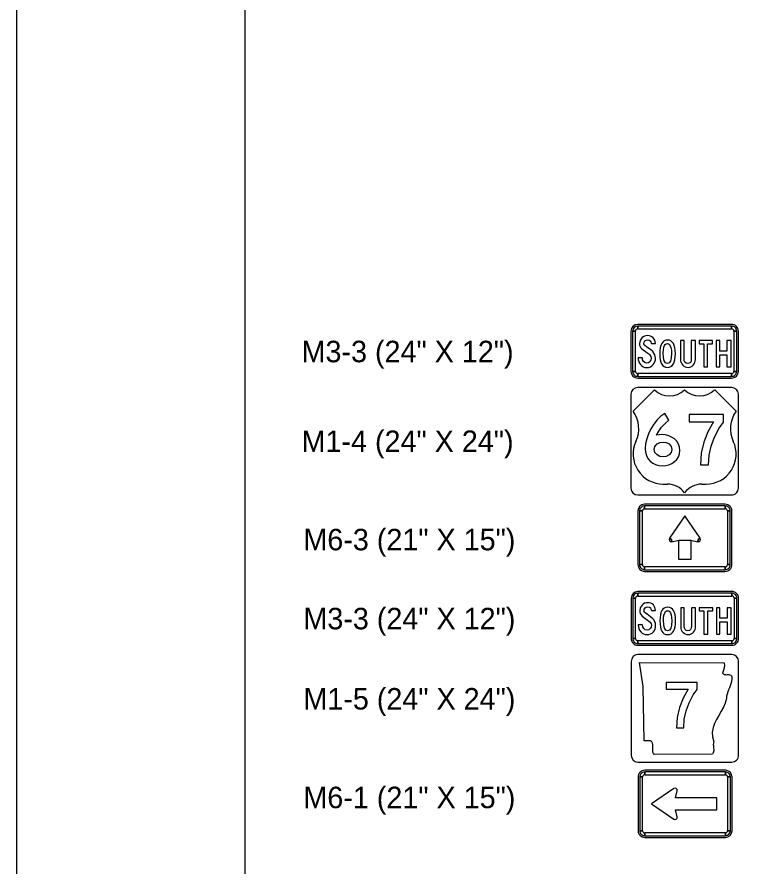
# Model space of a CAD drawing. Extents: x 1001568 to 1002149, y 1840825 to 1841423.
# Drawn here: x 1001886.41 to 1001900.1, y 1841178.92 to 1841194.75 of the extents above; entities that cross this region are included whole.
import ezdxf

# ---------------------------------------------------------------- set-up
doc = ezdxf.new("R2010")
doc.units = 0
for name, color, linetype in [('40', 7, 'Continuous'), ('R_No Plot', 7, 'Continuous'), ('SIGNS', 7, 'Continuous')]:
    doc.layers.add(name, color=color, linetype=linetype)

msp = doc.modelspace()

# ---------------------------------------------------------------- linework, layer by layer
at = {"layer": 'R_No Plot'}
msp.add_line((1001890.65, 1841210.667), (1001890.65, 1841148.127), dxfattribs=at)
msp.add_lwpolyline([(1001886.411, 1841210.667), (1001964.232, 1841210.667), (1001964.232, 1841207.694), (1001968.454, 1841207.694), (1001968.454, 1841206.882), (1001982.133, 1841206.882), (1001982.133, 1841148.127), (1001886.411, 1841148.127)], close=True, dxfattribs=at)
at = {"layer": 'SIGNS'}
for p, q in [((1001897.842, 1841188.897), (1001897.842, 1841188.147)), ((1001897.873, 1841188.897), (1001897.925, 1841188.897)), ((1001899.717, 1841189.022), (1001897.967, 1841189.022)), ((1001897.967, 1841188.939), (1001897.967, 1841188.991)), ((1001899.717, 1841188.991), (1001899.717, 1841188.939)), ((1001899.758, 1841188.897), (1001899.811, 1841188.897)), ((1001899.842, 1841188.147), (1001899.842, 1841188.897)), ((1001897.925, 1841188.147), (1001897.873, 1841188.147)), ((1001897.967, 1841188.053), (1001897.967, 1841188.105)), ((1001899.717, 1841188.105), (1001899.717, 1841188.053)), ((1001899.811, 1841188.147), (1001899.758, 1841188.147)), ((1001897.967, 1841188.022), (1001899.717, 1841188.022)), ((1001898.283, 1841187.805), (1001897.883, 1841187.405)), ((1001899.717, 1841187.846), (1001897.967, 1841187.846)), ((1001899.8, 1841187.405), (1001899.401, 1841187.805)), ((1001897.842, 1841187.721), (1001897.842, 1841185.971)), ((1001899.842, 1841185.971), (1001899.842, 1841187.721)), ((1001898.442, 1841186.048), (1001898.522, 1841186.048)), ((1001899.161, 1841186.048), (1001899.241, 1841186.048)), ((1001897.842, 1841185.971), (1001897.842, 1841185.971)), ((1001897.967, 1841185.846), (1001899.717, 1841185.846)), ((1001899.596, 1841185.673), (1001898.096, 1841185.673)), ((1001898.096, 1841185.589), (1001898.096, 1841185.641)), ((1001899.596, 1841185.641), (1001899.596, 1841185.589)), ((1001897.971, 1841185.548), (1001897.971, 1841184.548)), ((1001898.002, 1841185.548), (1001898.054, 1841185.548)), ((1001899.637, 1841185.548), (1001899.689, 1841185.548)), ((1001899.721, 1841184.548), (1001899.721, 1841185.548)), ((1001898.596, 1841185.016), (1001898.56, 1841185.039)), ((1001898.605, 1841184.976), (1001898.596, 1841185.016)), ((1001899.096, 1841185.016), (1001899.086, 1841184.976)), ((1001899.131, 1841185.039), (1001899.096, 1841185.016)), ((1001898.054, 1841184.548), (1001898.002, 1841184.548)), ((1001898.096, 1841184.454), (1001898.096, 1841184.506)), ((1001899.596, 1841184.506), (1001899.596, 1841184.454)), ((1001899.689, 1841184.548), (1001899.637, 1841184.548)), ((1001898.096, 1841184.423), (1001899.596, 1841184.423)), ((1001899.721, 1841184.048), (1001897.971, 1841184.048)), ((1001897.971, 1841183.964), (1001897.971, 1841184.016)), ((1001899.721, 1841184.016), (1001899.721, 1841183.964)), ((1001897.846, 1841183.923), (1001897.846, 1841183.173)), ((1001897.877, 1841183.923), (1001897.929, 1841183.923)), ((1001899.762, 1841183.923), (1001899.814, 1841183.923)), ((1001899.846, 1841183.173), (1001899.846, 1841183.923)), ((1001897.929, 1841183.173), (1001897.877, 1841183.173)), ((1001897.971, 1841183.079), (1001897.971, 1841183.131)), ((1001897.971, 1841183.048), (1001899.721, 1841183.048)), ((1001899.721, 1841183.131), (1001899.721, 1841183.079)), ((1001899.814, 1841183.173), (1001899.762, 1841183.173)), ((1001899.721, 1841182.872), (1001897.971, 1841182.872)), ((1001897.846, 1841182.747), (1001897.846, 1841180.997)), ((1001899.846, 1841180.997), (1001899.846, 1841182.747)), ((1001897.846, 1841180.997), (1001897.846, 1841180.997)), ((1001897.971, 1841180.872), (1001899.721, 1841180.872)), ((1001899.6, 1841180.719), (1001898.1, 1841180.719)), ((1001898.1, 1841180.636), (1001898.1, 1841180.688)), ((1001899.6, 1841180.688), (1001899.6, 1841180.636)), ((1001897.975, 1841180.594), (1001897.975, 1841179.594)), ((1001898.006, 1841180.594), (1001898.058, 1841180.594)), ((1001899.641, 1841180.594), (1001899.693, 1841180.594)), ((1001899.725, 1841179.594), (1001899.725, 1841180.594)), ((1001898.64, 1841180.379), (1001898.225, 1841180.094)), ((1001898.673, 1841180.203), (1001898.703, 1841180.335)), ((1001899.443, 1841180.203), (1001898.673, 1841180.203)), ((1001899.443, 1841180.203), (1001899.443, 1841180.203)), ((1001899.443, 1841179.985), (1001899.443, 1841180.203)), ((1001898.225, 1841180.094), (1001898.225, 1841180.094)), ((1001898.225, 1841180.094), (1001898.64, 1841179.809)), ((1001898.703, 1841179.853), (1001898.673, 1841179.985)), ((1001898.673, 1841179.985), (1001899.443, 1841179.985)), ((1001898.058, 1841179.594), (1001898.006, 1841179.594)), ((1001898.1, 1841179.5), (1001898.1, 1841179.552)), ((1001899.6, 1841179.552), (1001899.6, 1841179.5)), ((1001899.693, 1841179.594), (1001899.641, 1841179.594)), ((1001898.1, 1841179.469), (1001899.6, 1841179.469))]:
    msp.add_line(p, q, dxfattribs=at)
for points in [[(1001897.873, 1841188.897), (1001897.873, 1841188.147), (1001897.925, 1841188.147), (1001897.925, 1841188.897), (1001897.873, 1841188.897), (1001897.873, 1841188.897)], [(1001899.717, 1841188.991), (1001897.967, 1841188.991), (1001897.967, 1841188.939), (1001899.717, 1841188.939), (1001899.717, 1841188.991), (1001899.717, 1841188.991)], [(1001899.811, 1841188.147), (1001899.811, 1841188.897), (1001899.758, 1841188.897), (1001899.758, 1841188.147), (1001899.811, 1841188.147), (1001899.811, 1841188.147)], [(1001897.975, 1841188.402), (1001897.975, 1841188.397), (1001897.978, 1841188.362), (1001897.986, 1841188.33), (1001898, 1841188.3), (1001898.02, 1841188.273), (1001898.044, 1841188.249), (1001898.072, 1841188.233), (1001898.103, 1841188.222), (1001898.137, 1841188.219), (1001898.172, 1841188.222), (1001898.203, 1841188.232), (1001898.23, 1841188.249), (1001898.255, 1841188.272), (1001898.274, 1841188.298), (1001898.287, 1841188.327), (1001898.296, 1841188.359), (1001898.298, 1841188.394), (1001898.295, 1841188.427), (1001898.285, 1841188.458), (1001898.269, 1841188.488), (1001898.247, 1841188.517), (1001898.204, 1841188.554), (1001898.137, 1841188.599), (1001898.094, 1841188.632), (1001898.084, 1841188.649), (1001898.081, 1841188.668), (1001898.086, 1841188.694), (1001898.101, 1841188.715), (1001898.124, 1841188.73), (1001898.15, 1841188.735), (1001898.179, 1841188.73), (1001898.199, 1841188.716), (1001898.21, 1841188.697), (1001898.219, 1841188.668), (1001898.298, 1841188.668), (1001898.285, 1841188.726), (1001898.255, 1841188.772), (1001898.233, 1841188.79), (1001898.208, 1841188.803), (1001898.179, 1841188.811), (1001898.148, 1841188.814), (1001898.119, 1841188.811), (1001898.092, 1841188.803), (1001898.067, 1841188.789), (1001898.045, 1841188.769), (1001898.012, 1841188.721), (1001898.001, 1841188.666), (1001898.004, 1841188.637), (1001898.012, 1841188.611), (1001898.026, 1841188.586), (1001898.045, 1841188.564), (1001898.138, 1841188.498), (1001898.173, 1841188.472), (1001898.194, 1841188.452), (1001898.213, 1841188.423), (1001898.219, 1841188.393), (1001898.214, 1841188.359), (1001898.197, 1841188.33), (1001898.17, 1841188.309), (1001898.137, 1841188.302), (1001898.102, 1841188.31), (1001898.075, 1841188.334), (1001898.059, 1841188.365), (1001898.054, 1841188.402)], [(1001898.764, 1841188.721), (1001898.764, 1841188.366), (1001898.767, 1841188.337), (1001898.775, 1841188.31), (1001898.787, 1841188.286), (1001898.805, 1841188.263), (1001898.826, 1841188.245), (1001898.85, 1841188.231), (1001898.876, 1841188.223), (1001898.905, 1841188.221), (1001898.932, 1841188.223), (1001898.958, 1841188.232), (1001898.981, 1841188.246), (1001899.002, 1841188.265), (1001899.019, 1841188.288), (1001899.031, 1841188.312), (1001899.038, 1841188.339), (1001899.041, 1841188.367), (1001899.041, 1841188.721), (1001898.966, 1841188.721), (1001898.966, 1841188.37), (1001898.962, 1841188.339), (1001898.949, 1841188.315), (1001898.926, 1841188.297), (1001898.897, 1841188.292), (1001898.869, 1841188.298), (1001898.848, 1841188.316), (1001898.835, 1841188.341), (1001898.831, 1841188.37), (1001898.831, 1841188.721)], [(1001899.198, 1841188.23), (1001899.269, 1841188.23), (1001899.269, 1841188.659), (1001899.361, 1841188.659), (1001899.361, 1841188.721), (1001899.109, 1841188.721), (1001899.109, 1841188.659), (1001899.198, 1841188.659)], [(1001899.428, 1841188.23), (1001899.495, 1841188.23), (1001899.495, 1841188.455), (1001899.63, 1841188.455), (1001899.63, 1841188.23), (1001899.705, 1841188.23), (1001899.705, 1841188.721), (1001899.63, 1841188.721), (1001899.63, 1841188.524), (1001899.495, 1841188.524), (1001899.495, 1841188.721), (1001899.428, 1841188.721)], [(1001897.967, 1841188.053), (1001899.717, 1841188.053), (1001899.717, 1841188.105), (1001897.967, 1841188.105), (1001897.967, 1841188.053), (1001897.967, 1841188.053)], [(1001899.134, 1841186.407), (1001899.286, 1841186.407), (1001899.298, 1841186.584), (1001899.335, 1841186.757), (1001899.397, 1841186.924), (1001899.484, 1841187.088), (1001899.568, 1841187.2), (1001899.568, 1841187.347), (1001898.923, 1841187.347), (1001898.923, 1841187.206), (1001899.377, 1841187.206), (1001899.272, 1841187.022), (1001899.197, 1841186.827), (1001899.151, 1841186.622)], [(1001899.596, 1841185.641), (1001898.096, 1841185.641), (1001898.096, 1841185.589), (1001899.596, 1841185.589), (1001899.596, 1841185.641), (1001899.596, 1841185.641)], [(1001898.002, 1841185.548), (1001898.002, 1841184.548), (1001898.054, 1841184.548), (1001898.054, 1841185.548), (1001898.002, 1841185.548), (1001898.002, 1841185.548)], [(1001898.846, 1841185.454), (1001898.56, 1841185.039), (1001898.596, 1841185.016), (1001898.605, 1841184.976), (1001898.736, 1841185.006), (1001898.955, 1841185.006), (1001899.086, 1841184.976), (1001899.096, 1841185.016), (1001899.131, 1841185.039), (1001898.846, 1841185.454), (1001898.846, 1841185.454)], [(1001899.689, 1841184.548), (1001899.689, 1841185.548), (1001899.637, 1841185.548), (1001899.637, 1841184.548), (1001899.689, 1841184.548), (1001899.689, 1841184.548)], [(1001898.955, 1841184.641), (1001898.736, 1841184.641), (1001898.736, 1841185.006), (1001898.955, 1841185.006), (1001898.955, 1841184.641), (1001898.955, 1841184.641)], [(1001898.096, 1841184.454), (1001899.596, 1841184.454), (1001899.596, 1841184.506), (1001898.096, 1841184.506), (1001898.096, 1841184.454), (1001898.096, 1841184.454)], [(1001899.721, 1841184.016), (1001897.971, 1841184.016), (1001897.971, 1841183.964), (1001899.721, 1841183.964), (1001899.721, 1841184.016), (1001899.721, 1841184.016)], [(1001897.877, 1841183.923), (1001897.877, 1841183.173), (1001897.929, 1841183.173), (1001897.929, 1841183.923), (1001897.877, 1841183.923), (1001897.877, 1841183.923)], [(1001897.979, 1841183.428), (1001897.979, 1841183.423), (1001897.982, 1841183.388), (1001897.99, 1841183.356), (1001898.004, 1841183.326), (1001898.024, 1841183.299), (1001898.048, 1841183.275), (1001898.076, 1841183.258), (1001898.107, 1841183.248), (1001898.141, 1841183.245), (1001898.175, 1841183.248), (1001898.206, 1841183.258), (1001898.234, 1841183.274), (1001898.259, 1841183.297), (1001898.278, 1841183.324), (1001898.291, 1841183.353), (1001898.3, 1841183.385), (1001898.302, 1841183.419), (1001898.299, 1841183.453), (1001898.289, 1841183.484), (1001898.273, 1841183.514), (1001898.251, 1841183.542), (1001898.208, 1841183.579), (1001898.141, 1841183.625), (1001898.097, 1841183.658), (1001898.088, 1841183.675), (1001898.085, 1841183.694), (1001898.09, 1841183.719), (1001898.105, 1841183.741), (1001898.128, 1841183.755), (1001898.154, 1841183.76), (1001898.182, 1841183.755), (1001898.203, 1841183.742), (1001898.214, 1841183.722), (1001898.223, 1841183.694), (1001898.302, 1841183.694), (1001898.289, 1841183.752), (1001898.259, 1841183.798), (1001898.237, 1841183.816), (1001898.212, 1841183.829), (1001898.183, 1841183.837), (1001898.152, 1841183.839), (1001898.123, 1841183.836), (1001898.096, 1841183.828), (1001898.071, 1841183.814), (1001898.049, 1841183.795), (1001898.016, 1841183.747), (1001898.005, 1841183.691), (1001898.008, 1841183.663), (1001898.016, 1841183.636), (1001898.03, 1841183.612), (1001898.049, 1841183.59), (1001898.142, 1841183.523), (1001898.177, 1841183.497), (1001898.198, 1841183.478), (1001898.217, 1841183.449), (1001898.223, 1841183.419), (1001898.218, 1841183.385), (1001898.201, 1841183.356), (1001898.174, 1841183.335), (1001898.141, 1841183.328), (1001898.106, 1841183.336), (1001898.079, 1841183.359), (1001898.063, 1841183.39), (1001898.058, 1841183.428)], [(1001899.814, 1841183.173), (1001899.814, 1841183.923), (1001899.762, 1841183.923), (1001899.762, 1841183.173), (1001899.814, 1841183.173), (1001899.814, 1841183.173)], [(1001898.768, 1841183.746), (1001898.768, 1841183.391), (1001898.771, 1841183.362), (1001898.779, 1841183.336), (1001898.791, 1841183.311), (1001898.809, 1841183.289), (1001898.83, 1841183.27), (1001898.854, 1841183.257), (1001898.88, 1841183.249), (1001898.908, 1841183.246), (1001898.936, 1841183.249), (1001898.962, 1841183.257), (1001898.985, 1841183.271), (1001899.006, 1841183.291), (1001899.023, 1841183.314), (1001899.035, 1841183.338), (1001899.042, 1841183.364), (1001899.045, 1841183.393), (1001899.045, 1841183.746), (1001898.97, 1841183.746), (1001898.97, 1841183.396), (1001898.966, 1841183.365), (1001898.953, 1841183.341), (1001898.93, 1841183.323), (1001898.901, 1841183.317), (1001898.873, 1841183.323), (1001898.852, 1841183.342), (1001898.839, 1841183.366), (1001898.835, 1841183.396), (1001898.835, 1841183.746)], [(1001899.202, 1841183.256), (1001899.273, 1841183.256), (1001899.273, 1841183.685), (1001899.365, 1841183.685), (1001899.365, 1841183.746), (1001899.113, 1841183.746), (1001899.113, 1841183.685), (1001899.202, 1841183.685)], [(1001899.432, 1841183.256), (1001899.499, 1841183.256), (1001899.499, 1841183.481), (1001899.634, 1841183.481), (1001899.634, 1841183.256), (1001899.709, 1841183.256), (1001899.709, 1841183.746), (1001899.634, 1841183.746), (1001899.634, 1841183.55), (1001899.499, 1841183.55), (1001899.499, 1841183.746), (1001899.432, 1841183.746)], [(1001897.971, 1841183.079), (1001899.721, 1841183.079), (1001899.721, 1841183.131), (1001897.971, 1841183.131), (1001897.971, 1841183.079), (1001897.971, 1841183.079)], [(1001899.576, 1841182.718), (1001899.58, 1841182.699), (1001899.582, 1841182.679), (1001899.581, 1841182.66), (1001899.579, 1841182.641), (1001899.575, 1841182.622), (1001899.57, 1841182.603), (1001899.565, 1841182.584), (1001899.559, 1841182.566), (1001899.554, 1841182.547), (1001899.549, 1841182.529), (1001899.563, 1841182.513), (1001899.58, 1841182.504), (1001899.6, 1841182.5), (1001899.621, 1841182.499), (1001899.642, 1841182.5), (1001899.663, 1841182.5), (1001899.682, 1841182.498), (1001899.699, 1841182.492), (1001899.712, 1841182.48), (1001899.72, 1841182.46), (1001899.721, 1841182.414), (1001899.715, 1841182.371), (1001899.704, 1841182.331), (1001899.69, 1841182.292), (1001899.674, 1841182.254), (1001899.658, 1841182.216), (1001899.643, 1841182.178), (1001899.631, 1841182.138), (1001899.623, 1841182.097), (1001899.621, 1841182.053), (1001899.599, 1841181.971), (1001899.565, 1841181.892), (1001899.524, 1841181.817), (1001899.48, 1841181.742), (1001899.437, 1841181.667), (1001899.399, 1841181.591), (1001899.371, 1841181.513), (1001899.357, 1841181.43), (1001899.36, 1841181.343), (1001899.386, 1841181.249), (1001899.378, 1841181.226), (1001899.375, 1841181.202), (1001899.376, 1841181.178), (1001899.379, 1841181.154), (1001899.382, 1841181.13), (1001899.385, 1841181.107), (1001899.386, 1841181.084), (1001899.382, 1841181.062), (1001899.374, 1841181.041), (1001899.359, 1841181.021), (1001898.275, 1841181.011), (1001898.26, 1841181.031), (1001898.252, 1841181.055), (1001898.248, 1841181.081), (1001898.248, 1841181.109), (1001898.249, 1841181.139), (1001898.249, 1841181.168), (1001898.247, 1841181.197), (1001898.241, 1841181.224), (1001898.23, 1841181.248), (1001898.212, 1841181.269), (1001898.086, 1841181.269), (1001898.067, 1841182.281), (1001898.004, 1841182.728), (1001899.576, 1841182.718), (1001899.576, 1841182.718)], [(1001898.688, 1841181.512), (1001898.824, 1841181.512), (1001898.835, 1841181.67), (1001898.868, 1841181.825), (1001898.924, 1841181.975), (1001899.001, 1841182.121), (1001899.076, 1841182.221), (1001899.076, 1841182.353), (1001898.499, 1841182.353), (1001898.499, 1841182.227), (1001898.906, 1841182.227), (1001898.812, 1841182.062), (1001898.744, 1841181.888), (1001898.703, 1841181.704)], [(1001899.6, 1841180.688), (1001898.1, 1841180.688), (1001898.1, 1841180.636), (1001899.6, 1841180.636), (1001899.6, 1841180.688), (1001899.6, 1841180.688)], [(1001898.006, 1841180.594), (1001898.006, 1841179.594), (1001898.058, 1841179.594), (1001898.058, 1841180.594), (1001898.006, 1841180.594), (1001898.006, 1841180.594)], [(1001899.693, 1841179.594), (1001899.693, 1841180.594), (1001899.641, 1841180.594), (1001899.641, 1841179.594), (1001899.693, 1841179.594), (1001899.693, 1841179.594)], [(1001898.1, 1841179.5), (1001899.6, 1841179.5), (1001899.6, 1841179.552), (1001898.1, 1841179.552), (1001898.1, 1841179.5), (1001898.1, 1841179.5)]]:
    msp.add_lwpolyline(points, close=True, dxfattribs=at)
for points in [[(1001898.669, 1841188.476), (1001898.666, 1841188.536), (1001898.66, 1841188.587), (1001898.648, 1841188.631), (1001898.632, 1841188.667), (1001898.612, 1841188.694), (1001898.587, 1841188.714), (1001898.558, 1841188.726), (1001898.524, 1841188.73), (1001898.489, 1841188.726), (1001898.459, 1841188.714), (1001898.434, 1841188.694), (1001898.414, 1841188.667), (1001898.397, 1841188.631), (1001898.386, 1841188.587), (1001898.379, 1841188.536), (1001898.377, 1841188.476), (1001898.379, 1841188.416), (1001898.386, 1841188.364), (1001898.397, 1841188.32), (1001898.413, 1841188.285), (1001898.433, 1841188.256), (1001898.458, 1841188.237), (1001898.487, 1841188.225), (1001898.521, 1841188.221), (1001898.555, 1841188.225), (1001898.585, 1841188.237), (1001898.611, 1841188.256), (1001898.632, 1841188.285), (1001898.648, 1841188.32), (1001898.659, 1841188.364), (1001898.666, 1841188.416), (1001898.669, 1841188.476)], [(1001898.598, 1841188.478), (1001898.593, 1841188.397), (1001898.579, 1841188.339), (1001898.555, 1841188.304), (1001898.522, 1841188.292), (1001898.488, 1841188.304), (1001898.463, 1841188.342), (1001898.449, 1841188.404), (1001898.444, 1841188.491), (1001898.447, 1841188.549), (1001898.457, 1841188.597), (1001898.468, 1841188.626), (1001898.482, 1841188.647), (1001898.5, 1841188.66), (1001898.522, 1841188.664), (1001898.543, 1841188.66), (1001898.561, 1841188.646), (1001898.575, 1841188.623), (1001898.586, 1841188.59), (1001898.595, 1841188.539), (1001898.598, 1841188.478)], [(1001897.967, 1841187.846), (1001897.967, 1841187.846)], [(1001899.717, 1841187.846), (1001899.717, 1841187.846)], [(1001897.842, 1841187.721), (1001897.842, 1841187.721)], [(1001898.55, 1841187.241), (1001898.475, 1841187.365), (1001898.4, 1841187.31), (1001898.331, 1841187.244), (1001898.269, 1841187.167), (1001898.214, 1841187.079), (1001898.167, 1841186.985), (1001898.135, 1841186.892), (1001898.115, 1841186.8), (1001898.109, 1841186.709), (1001898.114, 1841186.641), (1001898.131, 1841186.58), (1001898.159, 1841186.525), (1001898.199, 1841186.478), (1001898.247, 1841186.438), (1001898.302, 1841186.411), (1001898.364, 1841186.394), (1001898.432, 1841186.389), (1001898.492, 1841186.393), (1001898.55, 1841186.408), (1001898.602, 1841186.432), (1001898.652, 1841186.466), (1001898.696, 1841186.509), (1001898.728, 1841186.558), (1001898.747, 1841186.612), (1001898.753, 1841186.672), (1001898.746, 1841186.735), (1001898.727, 1841186.793), (1001898.695, 1841186.845), (1001898.65, 1841186.89), (1001898.6, 1841186.925), (1001898.545, 1841186.949), (1001898.485, 1841186.964), (1001898.419, 1841186.969), (1001898.318, 1841186.959), (1001898.36, 1841187.036), (1001898.413, 1841187.109), (1001898.477, 1841187.177), (1001898.55, 1841187.241)], [(1001898.274, 1841186.694), (1001898.288, 1841186.75), (1001898.328, 1841186.796), (1001898.38, 1841186.822), (1001898.439, 1841186.831), (1001898.498, 1841186.822), (1001898.551, 1841186.796), (1001898.592, 1841186.75), (1001898.606, 1841186.694), (1001898.592, 1841186.636), (1001898.551, 1841186.59), (1001898.498, 1841186.563), (1001898.439, 1841186.555), (1001898.38, 1841186.563), (1001898.328, 1841186.59), (1001898.288, 1841186.636), (1001898.274, 1841186.694)], [(1001897.967, 1841185.846), (1001897.967, 1841185.846)], [(1001899.717, 1841185.846), (1001899.717, 1841185.846)], [(1001898.673, 1841183.502), (1001898.67, 1841183.561), (1001898.663, 1841183.613), (1001898.652, 1841183.656), (1001898.636, 1841183.692), (1001898.616, 1841183.72), (1001898.591, 1841183.74), (1001898.562, 1841183.752), (1001898.528, 1841183.756), (1001898.493, 1841183.752), (1001898.463, 1841183.74), (1001898.438, 1841183.72), (1001898.417, 1841183.692), (1001898.401, 1841183.656), (1001898.39, 1841183.613), (1001898.383, 1841183.561), (1001898.381, 1841183.502), (1001898.383, 1841183.442), (1001898.39, 1841183.39), (1001898.401, 1841183.346), (1001898.417, 1841183.31), (1001898.437, 1841183.282), (1001898.462, 1841183.262), (1001898.491, 1841183.25), (1001898.525, 1841183.246), (1001898.559, 1841183.25), (1001898.589, 1841183.262), (1001898.615, 1841183.282), (1001898.636, 1841183.31), (1001898.652, 1841183.346), (1001898.663, 1841183.39), (1001898.67, 1841183.442), (1001898.673, 1841183.502)], [(1001898.602, 1841183.504), (1001898.597, 1841183.422), (1001898.583, 1841183.364), (1001898.559, 1841183.329), (1001898.525, 1841183.318), (1001898.492, 1841183.33), (1001898.467, 1841183.367), (1001898.453, 1841183.429), (1001898.448, 1841183.516), (1001898.451, 1841183.574), (1001898.46, 1841183.622), (1001898.472, 1841183.652), (1001898.486, 1841183.673), (1001898.504, 1841183.686), (1001898.525, 1841183.69), (1001898.547, 1841183.685), (1001898.564, 1841183.671), (1001898.579, 1841183.648), (1001898.59, 1841183.616), (1001898.599, 1841183.565), (1001898.602, 1841183.504)], [(1001897.971, 1841182.872), (1001897.971, 1841182.872)], [(1001899.721, 1841182.872), (1001899.721, 1841182.872)], [(1001897.846, 1841182.747), (1001897.846, 1841182.747)], [(1001897.971, 1841180.872), (1001897.971, 1841180.872)], [(1001899.721, 1841180.872), (1001899.721, 1841180.872)]]:
    msp.add_lwpolyline(points, dxfattribs=at)
for centre, radius, start, end in [((1001897.967, 1841188.897), 0.125, 90.0002, 179.9998), ((1001897.967, 1841188.897), 0.0937, 90.0002, 179.9998), ((1001897.967, 1841188.897), 0.0417, 90.0002, 179.9998), ((1001899.717, 1841188.897), 0.125, 360, 90.0002), ((1001899.717, 1841188.897), 0.0937, 360, 90.0002), ((1001899.717, 1841188.897), 0.0417, 360, 90.0002), ((1001897.967, 1841188.147), 0.125, 179.9998, 270.0001), ((1001897.967, 1841188.147), 0.0937, 179.9998, 270.0001), ((1001897.967, 1841188.147), 0.0417, 179.9998, 270.0001), ((1001899.717, 1841188.147), 0.125, 270.0001, 0.0003), ((1001899.717, 1841188.147), 0.0937, 270.0001, 0.0003), ((1001899.717, 1841188.147), 0.0417, 270.0001, 0.0003), ((1001897.967, 1841187.721), 0.125, 90.0002, 179.9998), ((1001898.562, 1841188.09), 0.399, 225.5729, 314.4272), ((1001899.121, 1841188.09), 0.399, 225.5729, 314.4272), ((1001899.717, 1841187.721), 0.125, 0, 90), ((1001897.429, 1841187.079), 0.559, 334.9895, 35.6629), ((1001900.254, 1841187.079), 0.559, 144.3372, 205.01), ((1001898.442, 1841186.607), 0.559, 154.9897, 270.0001), ((1001899.241, 1841186.607), 0.559, 270.0001, 25.0104), ((1001898.522, 1841185.648), 0.399, 36.8699, 90.0002), ((1001899.161, 1841185.648), 0.399, 90.0002, 143.13), ((1001897.967, 1841185.971), 0.125, 180, 270), ((1001899.717, 1841185.971), 0.125, 270.0001, 0.0003), ((1001898.096, 1841185.548), 0.125, 90.0002, 179.9998), ((1001898.096, 1841185.548), 0.0937, 90.0002, 179.9998), ((1001898.096, 1841185.548), 0.0417, 90.0002, 179.9998), ((1001899.596, 1841185.548), 0.125, 0, 90.0002), ((1001899.596, 1841185.548), 0.0937, 0, 90.0002), ((1001899.596, 1841185.548), 0.0417, 0, 90.0002), ((1001898.596, 1841185.016), 0.0417, 147.7246, 282.9506), ((1001899.096, 1841185.016), 0.0417, 257.0495, 32.2756), ((1001898.096, 1841184.548), 0.125, 179.9998, 270.0001), ((1001898.096, 1841184.548), 0.0937, 179.9998, 270.0001), ((1001898.096, 1841184.548), 0.0417, 179.9998, 270.0001), ((1001899.596, 1841184.548), 0.0937, 270.0001, 0.0003), ((1001899.596, 1841184.548), 0.0417, 270.0001, 0.0003), ((1001899.596, 1841184.548), 0.125, 270.0001, 0.0003), ((1001897.971, 1841183.923), 0.125, 90.0002, 179.9998), ((1001897.971, 1841183.923), 0.0937, 90.0002, 179.9998), ((1001899.721, 1841183.923), 0.125, 360, 90.0002), ((1001899.721, 1841183.923), 0.0937, 360, 90.0002), ((1001897.971, 1841183.923), 0.0417, 90.0002, 179.9998), ((1001899.721, 1841183.923), 0.0417, 360, 90.0002), ((1001897.971, 1841183.173), 0.125, 179.9998, 270.0001), ((1001897.971, 1841183.173), 0.0937, 179.9998, 270.0001), ((1001897.971, 1841183.173), 0.0417, 179.9998, 270.0001), ((1001899.721, 1841183.173), 0.125, 270.0001, 0.0003), ((1001899.721, 1841183.173), 0.0937, 270.0001, 0.0003), ((1001899.721, 1841183.173), 0.0417, 270.0001, 0.0003), ((1001897.971, 1841182.747), 0.125, 90.0002, 179.9998), ((1001899.721, 1841182.747), 0.125, 360, 90), ((1001897.971, 1841180.997), 0.125, 180, 270), ((1001899.721, 1841180.997), 0.125, 270.0001, 0.0003), ((1001898.1, 1841180.594), 0.125, 90.0001, 180.0003), ((1001898.1, 1841180.594), 0.0937, 90.0001, 180.0003), ((1001899.6, 1841180.594), 0.125, 359.9998, 90.0001), ((1001899.6, 1841180.594), 0.0937, 359.9998, 90.0001), ((1001898.1, 1841180.594), 0.0417, 90.0001, 180.0003), ((1001899.6, 1841180.594), 0.0417, 359.9998, 90.0001), ((1001898.662, 1841180.344), 0.0417, 347.0499, 122.2759), ((1001898.662, 1841179.844), 0.0417, 237.7244, 12.9504), ((1001898.1, 1841179.594), 0.125, 180, 270.0002), ((1001898.1, 1841179.594), 0.0937, 180, 270.0002), ((1001898.1, 1841179.594), 0.0417, 180, 270.0002), ((1001899.6, 1841179.594), 0.0937, 270.0002, 359.9998), ((1001899.6, 1841179.594), 0.0417, 270.0002, 359.9998), ((1001899.6, 1841179.594), 0.125, 270.0002, 359.9998)]:
    msp.add_arc(centre, radius, start, end, dxfattribs=at)

# ---------------------------------------------------------------- texts
at = {"layer": '40'}
for s, p in [('M3-3 (24" X 12")', (1001891.709, 1841188.317)), ('M1-4 (24" X 24")', (1001891.709, 1841186.646)), ('M6-3 (21" X 15")', (1001891.743, 1841184.815)), ('M3-3 (24" X 12")', (1001891.743, 1841183.344)), ('M1-5 (24" X 24")', (1001891.743, 1841181.85)), ('M6-1 (21" X 15")', (1001891.743, 1841180.013))]:
    msp.add_text(s, height=0.4, rotation=0, dxfattribs=at).set_placement(p)

doc.saveas('drawing.dxf')
